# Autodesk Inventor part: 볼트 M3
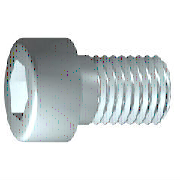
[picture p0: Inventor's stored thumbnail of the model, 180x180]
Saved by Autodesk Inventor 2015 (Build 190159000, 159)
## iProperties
IsCustomPart: 0
Created: 2012-02
Part Number: 볼트 M3
Material: 스테인리스강
Description: 6각 소켓 머리 캡 나사
Document SubType Name: Modeling
Standard: ISO 4762
Designer: mduedu
Standard Revision: Fourth edition 2004-03-01
Standards Organization: ISO
Language: ko-KR
Size Designation: M3 x 8
Categories: <MemberInstance><Categories><Category DisplayName="조임쇠" InternalName="e4da775c-781d-43d5-af7c-5136215cf5a6" Mnemonic="FSTN"><Category DisplayName="볼트" InternalN
Density: 7.75 g/cm^3
Appearance: 반광택
Author: mduedu
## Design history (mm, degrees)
sketch "스케치1"
  geometry: L1 (-0.867, 0)-(8, 0); L2 (8, 0)-(8, 1.5); L3 (8, 1.5)-(1.25, 1.5); L4 (1.25, 1.5)-(0.943, 1.5); L5 (0.943, 1.5)-(0, 1.5); L6 (0, 1.5)-(0, 2.75); L7 (0, 2.75)-(-3, 2.75); L8 (-3, 2.75)-(-3, 1.443); L9 (-3, 1.443)-(-1.7, 1.443); L10 (-1.7, 1.443)-(-0.867, 0); L11 (-5.2, 0)-(10.2, 0) reference; L12 (0, -0.55)-(0, 3.3) reference; L13 (1.25, 1.5)-(0, 1.5)
  constraints: 22 end point, 6 parallel, 2 collinear, 2 perpendicular, 1 horizontal, 1 point on line
  dimensions: "d1" = 6.75 distance from line of L3.end L2 (= GEL); "d2" = 0.30683 distance of L4.end L3.end (computed from GAL); "d3" = 3 distance between parallel lines of L8 L6 (= KOH); "d4" = 1.3 distance of L8.end L9.end (= INTI); "d5" = 60 deg angle of L10 L1; "d6" = 3 diameter of L3 L1 (= GD); "d7" = 3 diameter of L5 L1 (= BDM); "d8" = 2.88675 diameter of L9 L1 (= 1.1547 x SW); "d9" = 5.5 diameter of L7 L1 (= KOD); "d26" = 8 distance between parallel lines of L12 L2 (= NLG)
revolve "본체" sketch "스케치1" stored, may be unused: angle "d10" = 90 deg
sketch "스케치2"
  geometry: L1 (0, -3.85)-(0, 3.85) reference; L2 (-3.85, 0)-(3.85, 0) reference; L3 (1.443, 0)-(0.722, -1.25); L4 (0.722, -1.25)-(-0.722, -1.25); L5 (-0.722, -1.25)-(-1.443, 0); L6 (-1.443, 0)-(-0.722, 1.25); L7 (-0.722, 1.25)-(0.722, 1.25); L8 (0.722, 1.25)-(1.443, 0); 2 further points
  constraints: 12 end point, 1 coincident, 1 horizontal alignment, 1 point on line, 12 other
extrude "슬롯" join sketch "스케치2" stored distance "d11" = 10; taper "d12" = 0 deg
workplane "Work Plane1"
fillet "Fillet2" dims "d30" = 0.1 (= R)
body "Solid1"
fillet "모깎기1" dims "d17" = 0.3 (= RR)
feature "스레드" dims "d13" = 6.75 (= GEL), "d14" = 0
chamfer "모따기1" distance "d15" = 0.30673 (= -0.5 x SPD + 0.5 x GD); stored, may be unused: second distance "d16" = 0.30673 (= GUL), angle "d27" = 45 deg
other parameters: "GD" = 3 [user parameter; used in 2 equation terms], "NLG" = 8 [user parameter; used in 1 equation term], "GEL" = 6.75 [user parameter; used in 2 equation terms], "KOD" = 5.5 [user parameter; used in 1 equation term], "KOH" = 3 [user parameter; used in 1 equation term], "INTI" = 1.3 [user parameter; used in 1 equation term], "GAL" = 0.30673 (= 0.61345 x PTC) [user parameter; used in 1 equation term], "GUL" = 0.30673 (= 0.61345 x PTC) [user parameter; used in 1 equation term], "BDM" = 3 (= NND) [user parameter; used in 1 equation term], "SW" = 2.5 [user parameter; used in 2 equation terms], "RR" = 0.3 [user parameter; used in 1 equation term], "SPD" = 2.38655 (= NND - 1.2269 x PTC) [user parameter; used in 1 equation term], "d19" = 0, "d28" = 0, "d29" = 0, "R" = 0.1 [user parameter; used in 1 equation term], "TOA" = 30 deg [user parameter], "GD1" = 2.38655 (= THREADDIA - 1.2269 x PTC) [user parameter], "THREADDIA" = 3 [user parameter; used in 1 equation term], "FAWI" = 45 deg [user parameter], "PTC" = 0.5 [user parameter; used in 5 equation terms], "NND" = 3 [user parameter; used in 2 equation terms], "E0" = 2.8875 (= 1.155 x SW) [user parameter]
